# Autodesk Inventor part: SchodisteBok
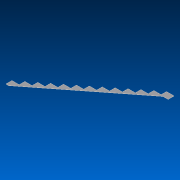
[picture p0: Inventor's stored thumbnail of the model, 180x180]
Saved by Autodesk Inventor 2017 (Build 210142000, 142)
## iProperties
Created: 2016-10
Part Number: SchodisteBok
Material: Všeobecné
Document SubType Name: Plech
Designer: navara
Density: 1 g/cm^3
Sheet Metal Rule: Výchozí
Appearance: Výchozí
Sheet Metal Width: 3941,610 mm
Sheet Metal Length: 1224,831 mm
Sheet Metal Area: 4827804,027 mm^2
Flat Pattern Width: 394.161 cm
Flat Pattern Length: 122.483 cm
Flat Pattern Area: 48278 cm^2
Beppe: SchodisteBok.ipt
Author: navara
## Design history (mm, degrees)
sketch "SkeletonNacrt" dims "d8" = 10
  geometry: L1 (0, 0)-(0, 192.308); L2 (0, 192.308)-(245.385, 192.308); L3 (245.385, 192.308)-(0, 0); L4 (245.385, 192.308)-(245.385, 384.615); L5 (245.385, 384.615)-(490.769, 384.615); L6 (490.769, 384.615)-(490.769, 576.923); L7 (490.769, 576.923)-(736.154, 576.923); L8 (736.154, 576.923)-(736.154, 769.231); L9 (736.154, 769.231)-(981.538, 769.231); L10 (981.538, 769.231)-(981.538, 961.538); L11 (981.538, 961.538)-(1226.923, 961.538); L12 (1226.923, 961.538)-(1226.923, 1153.846); L13 (1226.923, 1153.846)-(1472.308, 1153.846); L14 (1472.308, 1153.846)-(1472.308, 1346.154); L15 (1472.308, 1346.154)-(1717.692, 1346.154); L16 (1717.692, 1346.154)-(1717.692, 1538.462); L17 (1717.692, 1538.462)-(1963.077, 1538.462); L18 (1963.077, 1538.462)-(1963.077, 1730.769); L19 (1963.077, 1730.769)-(2208.462, 1730.769); L20 (2208.462, 1730.769)-(2208.462, 1923.077); L21 (2208.462, 1923.077)-(2453.846, 1923.077); L22 (2453.846, 1923.077)-(2453.846, 2115.385); L23 (2453.846, 2115.385)-(2699.231, 2115.385); L24 (2699.231, 2115.385)-(2699.231, 2307.692); L25 (2699.231, 2307.692)-(2944.615, 2307.692); L26 (2944.615, 2307.692)-(2944.615, 2500); L27 (2944.615, 2500)-(3190, 2500); L28 (0, 0)-(3190, 0); L29 (3190, 0)-(3190, 2500)
  constraints: 58 end point, 2 perpendicular, 1 horizontal, 1 vertical, 61 other
  dimensions: "d0" = 192.30769 distance of L1.start L1.end (= VyskaSchodu); "d1" = 245.38462 distance of L1.end L2.end (= DelkaSchodu); "d2" = 311.7625 distance of L2.end L1.start (derived); "d5" = 311.7625 distance of L1.end L4.end (= d2); "d10" = 3190 distance of L1.start L28.end (= DelkaSchodiste); "d11" = 2500 distance of L28.end L29.end (= VyskaSchodiste)
node "SmerSchodu"
sketch "Náčrt4"
  geometry: L1 (-10, 0)-(-10, 202.308); L2 (-10, 0)-(-10, 202.308); L3 (295.385, 202.308)-(295.385, 167.967); L4 (295.385, 167.967)-(81.058, 0); L5 (81.058, 0)-(-10, 0); L6 (0, 0)-(245.385, 192.308); L7 (-10, 202.308)-(295.385, 202.308); L8 (0, 192.308)-(245.385, 192.308) reference; L9 (0, 0)-(0, 192.308) reference
  constraints: 14 end point, 1 collinear, 1 parallel, 1 perpendicular, 1 point on line, 1 vertical
  dimensions: "d43" = 50 distance between parallel lines of L4 L6; "d44" = 50 distance from line of L6.end L3; "d51" = 10 distance between parallel lines of L7 L8; "d52" = 10 distance between parallel lines of L1 L9
extrude "PrvniZub" new body sketch "Náčrt4" distance "d41" = 5 (= Tloušťka); taper "d42" = 0 deg
sketch "Náčrt3"
  geometry: L1 (245.385, 192.308)-(245.385, 384.615) reference; L2 (245.385, 384.615)-(490.769, 384.615) reference; L3 (235.385, 142.308)-(235.385, 394.615); L4 (235.385, 394.615)-(540.769, 394.615); L5 (540.769, 394.615)-(540.769, 360.275); L6 (540.769, 360.275)-(262.643, 142.308); L7 (262.643, 142.308)-(235.385, 142.308); L8 (245.385, 192.308)-(490.769, 384.615)
  constraints: 12 end point, 2 parallel, 2 perpendicular, 1 vertical
  dimensions: "d30" = 10 distance between parallel lines of L3 L1; "d31" = 10 distance between parallel lines of L4 L2; "d37" = 50 distance between parallel lines of L6 L8; "d38" = 50 distance from line of L2.end L5; "d39" = 50 distance from line of L1.start L7
extrude "PrubeznyZub" join sketch "Náčrt3" distance "d32" = 5 (= Tloušťka); taper "d33" = 0 deg
pattern_linear "PrubezneZuby" dims "d36" = 311.7625 (= d2)
sketch "Náčrt5"
  geometry: L1 (3190, 0)-(3190, 2500) reference; L2 (3190, 2500)-(2934.615, 2500); L3 (2934.615, 2500)-(2934.615, 2236.33); L4 (3190, 2500)-(3190, 2299.855); L5 (3828, 3000)-(-638, -500) reference; L6 (3190, 2299.855)-(3015.674, 2299.855); L7 (2934.615, 2236.33)-(3015.674, 2299.855); L8 (3015.674, 2299.855)-(2934.615, 2299.855)
  constraints: 12 end point, 3 parallel, 3 point on line, 1 collinear, 1 horizontal, 1 perpendicular
  dimensions: "d46" = 255.38462 distance of L1.end L2.end (computed from DelkaSchodu); "d50" = 50 distance between parallel lines of L5 L7
extrude "PosledniZub" join sketch "Náčrt5" distance "d48" = 5 (= Tloušťka); taper "d49" = 0 deg
node "Těleso2"
feature "Definice1"
other parameters: "VyskaSchodiste" = 2500 [user parameter; used in 2 equation terms], "DelkaSchodiste" = 3190 (computed from DelkaSchodu, PocetSchodu) [user parameter; used in 1 equation term], "VyskaSchodu" = 192.30769 (computed from VyskaSchodiste, PocetSchodu) [user parameter; used in 2 equation terms], "DelkaSchodu" = 245.38462 (computed from VyskaSchodu) [user parameter; used in 3 equation terms], "Tloušťka" = 5 (derived), "KSoučinitel" = 4.4, "PoloměrOhybu" = 5 (= Tloušťka), "ŠířkaVýštipu" = 5 (= Tloušťka), "HloubkaVýštipu" = 2.5 (= 0.5 x Tloušťka), "MezeraVystřižení" = 0.01, "PřechodovýPoloměr" = 5 (= PoloměrOhybu), "VelikostJacobihoPoloměru" = 5 (= Tloušťka), "VelikostMezery" = 5 (= Tloušťka), "DelkaSchodu" = 245.38462, "VyskaSchodu" = 192.30769, "HloubkaVýštipu" = 2.5, "PoloměrOhybu" = 5, "PřechodovýPoloměr" = 5, "Tloušťka" = 5, "VelikostJacobihoPoloměru" = 5, "VelikostMezery" = 5, "ŠířkaVýštipu" = 5
